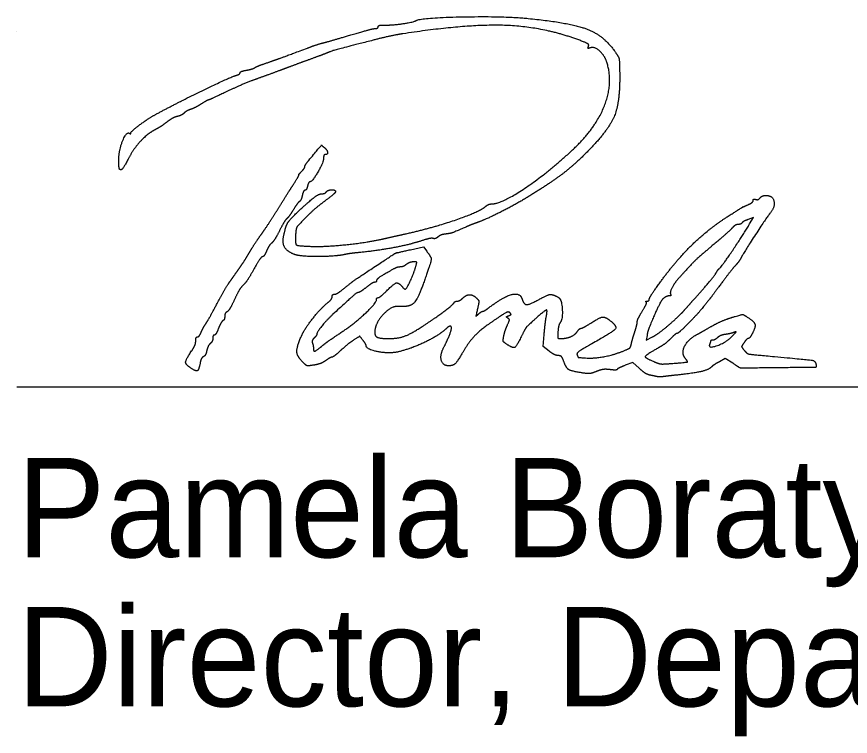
# Model space of a CAD drawing. Extents: x 0 to 34, y 0 to 22.
# Drawn here: x 24.5 to 25.674, y 7.199 to 8.213 of the extents above; entities that cross this region are included whole.
import ezdxf

# ---------------------------------------------------------------- set-up
doc = ezdxf.new("R2010")
doc.units = 0
doc.layers.add('SH_Data', color=7, linetype='Continuous')
doc.layers.add('SH_Text', color=7, linetype='Continuous')

msp = doc.modelspace()

# ---------------------------------------------------------------- linework, layer by layer
at = {"layer": 'SH_Data'}
for p, q in [((24.5, 8.191), (24.5, 8.191)), ((24.5, 7.691), (28, 7.691))]:
    msp.add_line(p, q, dxfattribs=at)
at = {"layer": 'SH_Text'}
for points in [[(25.5318, 7.9205), (25.5372, 7.9294), (25.5298, 7.9268)], [(25.0545, 7.8843), (25.0725, 7.8883), (25.0772, 7.8822)], [(25.2494, 7.7415), (25.2411, 7.7478), (25.2426, 7.7649)], [(25.3874, 7.7635), (25.3864, 7.757), (25.3951, 7.7614)], [(25.3764, 7.7172), (25.3672, 7.7254), (25.3567, 7.7214)], [(25.5083, 7.7242), (25.4976, 7.731), (25.4892, 7.7264)]]:
    msp.add_lwpolyline(points, dxfattribs=at)
for points in [[(25.0179, 8.2007), (25.0275, 8.2004), (25.0585, 8.2047), (25.0619, 8.2069)], [(25.0619, 8.2069), (25.0687, 8.2111), (25.1857, 8.2134), (25.2201, 8.21)], [(25.2201, 8.21), (25.2794, 8.2041), (25.3269, 8.1858), (25.3427, 8.1628)], [(24.9721, 8.1873), (24.9882, 8.192), (25.0031, 8.1959), (25.0051, 8.1959)], [(25.0051, 8.1959), (25.0072, 8.1959), (25.0089, 8.1971), (25.0089, 8.1984)], [(25.0089, 8.1984), (25.0089, 8.1998), (25.0129, 8.2008), (25.0179, 8.2007)], [(25.2926, 8.1792), (25.242, 8.1982), (25.1341, 8.2022), (25.0437, 8.1884)], [(24.9333, 8.1761), (24.9386, 8.1775), (24.9561, 8.1825), (24.9721, 8.1873)], [(25.0437, 8.1884), (25.0345, 8.187), (25.0145, 8.1827), (24.9993, 8.1787)], [(24.8529, 8.1477), (24.8676, 8.1528), (24.8741, 8.1552), (24.9093, 8.1683)], [(24.9093, 8.1683), (24.9172, 8.1713), (24.928, 8.1748), (24.9333, 8.1761)], [(24.9993, 8.1787), (24.9483, 8.1655), (24.944, 8.1643), (24.9333, 8.1599)], [(25.3049, 8.1706), (25.3059, 8.1731), (25.3024, 8.1755), (25.2926, 8.1792)], [(25.3073, 8.1685), (25.3047, 8.1675), (25.304, 8.1682), (25.3049, 8.1706)], [(25.3307, 8.1486), (25.3274, 8.1584), (25.313, 8.1707), (25.3073, 8.1685)], [(24.9333, 8.1599), (24.9307, 8.1589), (24.9204, 8.1551), (24.9105, 8.1515)], [(25.3427, 8.1628), (25.3476, 8.1555), (25.3486, 8.1512), (25.3489, 8.1333)], [(24.8349, 8.1405), (24.8362, 8.1415), (24.8443, 8.1448), (24.8529, 8.1477)], [(24.9105, 8.1515), (24.9006, 8.1479), (24.8855, 8.1423), (24.8769, 8.1391)], [(25.2852, 8.0274), (25.3161, 8.0568), (25.34, 8.1204), (25.3307, 8.1486)], [(24.8091, 8.1299), (24.8121, 8.1308), (24.8145, 8.1324), (24.8145, 8.1334)], [(24.8145, 8.1334), (24.8145, 8.1345), (24.8185, 8.1362), (24.8235, 8.1371)], [(24.8235, 8.1371), (24.8284, 8.138), (24.8336, 8.1396), (24.8349, 8.1405)], [(24.8769, 8.1391), (24.8683, 8.1358), (24.8521, 8.1299), (24.8409, 8.1259)], [(25.3489, 8.1333), (25.3496, 8.0926), (25.3335, 8.0529), (25.3041, 8.023)], [(24.6969, 8.0755), (24.7271, 8.0918), (24.8007, 8.1274), (24.8091, 8.1299)], [(24.8409, 8.1259), (24.8297, 8.1219), (24.8093, 8.1134), (24.7957, 8.1069)], [(24.7957, 8.1069), (24.782, 8.1004), (24.7704, 8.0951), (24.7698, 8.0951)], [(24.7598, 8.0895), (24.7549, 8.0864), (24.7482, 8.083), (24.745, 8.082)], [(24.7698, 8.0951), (24.7693, 8.0951), (24.7648, 8.0926), (24.7598, 8.0895)], [(24.6609, 8.0489), (24.6609, 8.0511), (24.6863, 8.0698), (24.6969, 8.0755)], [(24.7358, 8.0768), (24.734, 8.075), (24.7297, 8.0728), (24.7261, 8.072)], [(24.745, 8.082), (24.7418, 8.0809), (24.7376, 8.0786), (24.7358, 8.0768)], [(24.7113, 8.0639), (24.7067, 8.0603), (24.6995, 8.0557), (24.6954, 8.0536)], [(24.7261, 8.072), (24.7226, 8.0711), (24.7159, 8.0675), (24.7113, 8.0639)], [(24.6954, 8.0536), (24.685, 8.0482), (24.6651, 8.0274), (24.6589, 8.0153)], [(24.6437, 8.0111), (24.6438, 8.0242), (24.6545, 8.0508), (24.6586, 8.0483)], [(24.6586, 8.0483), (24.6599, 8.0475), (24.6609, 8.0478), (24.6609, 8.0489)], [(24.9111, 8.01), (24.9296, 8.0321), (24.9289, 8.0316), (24.933, 8.0282)], [(24.933, 8.0282), (24.9373, 8.0246), (24.9382, 8.0183), (24.9345, 8.0183)], [(25.1685, 7.9487), (25.1826, 7.9487), (25.2507, 7.9946), (25.2852, 8.0274)], [(24.9345, 8.0183), (24.9332, 8.0183), (24.9321, 8.0161), (24.9321, 8.0133)], [(25.3041, 8.023), (25.2855, 8.0041), (25.2531, 7.9792), (25.2226, 7.9603)], [(24.6451, 7.9973), (24.6443, 7.9981), (24.6437, 8.0043), (24.6437, 8.0111)], [(24.6589, 8.0153), (24.6522, 8.0024), (24.6469, 7.9955), (24.6451, 7.9973)], [(24.9057, 8.0013), (24.9057, 8.0025), (24.9081, 8.0064), (24.9111, 8.01)], [(24.9321, 8.0133), (24.9321, 8.0077), (24.9162, 7.9799), (24.913, 7.9799)], [(24.8971, 7.9895), (24.8966, 7.9895), (24.8983, 7.9917), (24.9009, 7.9943)], [(24.9009, 7.9943), (24.9035, 7.997), (24.9057, 8.0001), (24.9057, 8.0013)], [(24.8881, 7.9739), (24.8937, 7.9825), (24.8977, 7.9895), (24.8971, 7.9895)], [(24.8661, 7.9389), (24.8727, 7.9495), (24.8826, 7.9653), (24.8881, 7.9739)], [(24.9095, 7.9739), (24.9087, 7.9706), (24.907, 7.9679), (24.9058, 7.9679)], [(24.913, 7.9799), (24.9119, 7.9799), (24.9103, 7.9772), (24.9095, 7.9739)], [(24.8973, 7.939), (24.913, 7.9536), (24.9258, 7.9631), (24.9297, 7.9631)], [(24.9021, 7.9608), (24.9012, 7.9568), (24.8995, 7.953), (24.8982, 7.9522)], [(24.9058, 7.9679), (24.9047, 7.9679), (24.903, 7.9647), (24.9021, 7.9608)], [(24.9297, 7.9631), (24.9322, 7.9631), (24.9349, 7.9642), (24.9357, 7.9655)], [(24.9489, 7.9659), (24.9489, 7.9648), (24.9421, 7.9589), (24.9339, 7.9528)], [(24.9357, 7.9655), (24.9375, 7.9684), (24.9489, 7.9688), (24.9489, 7.9659)], [(25.2226, 7.9603), (25.2035, 7.9485), (25.1622, 7.9275), (25.1481, 7.9224)], [(25.5403, 7.9551), (25.5422, 7.9544), (25.545, 7.9554), (25.5466, 7.9573)], [(25.5466, 7.9573), (25.5482, 7.9592), (25.5519, 7.9607), (25.5548, 7.9607)], [(25.5548, 7.9607), (25.5643, 7.9607), (25.568, 7.9447), (25.5606, 7.9357)], [(24.8982, 7.9522), (24.8969, 7.9514), (24.8931, 7.9462), (24.8897, 7.9407)], [(24.9339, 7.9528), (24.9256, 7.9467), (24.9131, 7.9358), (24.9061, 7.9287)], [(25.0485, 7.9068), (25.0854, 7.915), (25.1517, 7.9379), (25.1603, 7.9454)], [(25.1603, 7.9454), (25.1624, 7.9472), (25.1661, 7.9487), (25.1685, 7.9487)], [(25.5001, 7.9304), (25.5191, 7.9426), (25.5209, 7.9437), (25.5291, 7.9474)], [(25.5291, 7.9474), (25.5334, 7.9493), (25.5369, 7.9521), (25.5369, 7.9537)], [(25.5369, 7.9537), (25.5369, 7.9552), (25.5384, 7.9559), (25.5403, 7.9551)], [(24.8443, 7.9059), (24.8497, 7.9134), (24.8595, 7.9282), (24.8661, 7.9389)], [(24.876, 7.9043), (24.8787, 7.9174), (24.8849, 7.9274), (24.8973, 7.939)], [(24.8897, 7.9407), (24.8863, 7.9352), (24.8822, 7.9296), (24.8806, 7.9283)], [(25.5606, 7.9357), (25.5564, 7.9307), (25.5236, 7.8802), (25.5204, 7.8741)], [(24.8806, 7.9283), (24.8789, 7.927), (24.8742, 7.9194), (24.8702, 7.9114)], [(24.9061, 7.9287), (24.8954, 7.9177), (24.8932, 7.914), (24.8927, 7.9058)], [(25.1481, 7.9224), (25.1435, 7.9207), (25.1364, 7.918), (25.1325, 7.9162)], [(25.4055, 7.8378), (25.4278, 7.8686), (25.4728, 7.9127), (25.5001, 7.9304)], [(25.5212, 7.9221), (25.5204, 7.9209), (25.518, 7.9199), (25.5158, 7.9199)], [(25.5298, 7.9268), (25.5258, 7.9254), (25.5219, 7.9233), (25.5212, 7.9221)], [(24.8702, 7.9114), (24.8662, 7.9034), (24.8611, 7.8954), (24.859, 7.8936)], [(25.1325, 7.9162), (25.1154, 7.9088), (25.1105, 7.9071), (25.1039, 7.9063)], [(25.507, 7.9145), (25.5043, 7.9116), (25.4918, 7.9005), (25.4793, 7.89)], [(25.489, 7.8575), (25.4918, 7.8595), (25.52, 7.901), (25.5318, 7.9205)], [(25.5158, 7.9199), (25.5136, 7.9199), (25.5097, 7.9175), (25.507, 7.9145)], [(24.8276, 7.8803), (24.8315, 7.8869), (24.839, 7.8985), (24.8443, 7.9059)], [(24.8913, 7.8775), (24.8809, 7.8814), (24.8737, 7.8938), (24.876, 7.9043)], [(24.8927, 7.9058), (24.8918, 7.8923), (24.8959, 7.8895), (24.9165, 7.8889)], [(24.9165, 7.8889), (24.9358, 7.8884), (24.9936, 7.8945), (25.0149, 7.8993)], [(25.0149, 7.8993), (25.0228, 7.9011), (25.0379, 7.9045), (25.0485, 7.9068)], [(25.0863, 7.9001), (25.0846, 7.9007), (25.0765, 7.899), (25.0683, 7.8963)], [(25.0931, 7.9022), (25.091, 7.9004), (25.0879, 7.8995), (25.0863, 7.9001)], [(25.1039, 7.9063), (25.1, 7.9059), (25.0952, 7.9041), (25.0931, 7.9022)], [(24.859, 7.8936), (24.8568, 7.8918), (24.8535, 7.8867), (24.8517, 7.8823)], [(25.0683, 7.8963), (25.0518, 7.891), (25.0067, 7.8826), (24.9829, 7.8803)], [(25.4793, 7.89), (25.4597, 7.8734), (25.448, 7.862), (25.4313, 7.8432)], [(24.8146, 7.8597), (24.8179, 7.8645), (24.8238, 7.8737), (24.8276, 7.8803)], [(24.8517, 7.8823), (24.8498, 7.8779), (24.8473, 7.8743), (24.846, 7.8743)], [(24.9625, 7.8776), (24.9488, 7.8746), (24.8993, 7.8745), (24.8913, 7.8775)], [(24.9829, 7.8803), (24.9746, 7.8795), (24.9654, 7.8783), (24.9625, 7.8776)], [(25.0005, 7.8579), (25.0322, 7.8789), (25.0335, 7.8796), (25.0545, 7.8843)], [(25.0772, 7.8822), (25.0838, 7.8734), (25.0836, 7.8685), (25.0759, 7.846)], [(24.846, 7.8743), (24.8447, 7.8743), (24.8393, 7.8664), (24.8339, 7.8568)], [(25.0486, 7.8635), (25.0461, 7.8615), (25.0421, 7.8599), (25.0399, 7.8599)], [(25.0585, 7.8671), (25.0557, 7.867), (25.0512, 7.8654), (25.0486, 7.8635)], [(25.0618, 7.8605), (25.0635, 7.8663), (25.0631, 7.8671), (25.0585, 7.8671)], [(25.5204, 7.8741), (25.5187, 7.8706), (25.5148, 7.8652), (25.5118, 7.8619)], [(24.801, 7.8405), (24.8051, 7.8463), (24.8112, 7.8549), (24.8146, 7.8597)], [(24.8339, 7.8568), (24.8286, 7.8471), (24.8219, 7.8371), (24.8191, 7.8346)], [(24.9613, 7.83), (24.975, 7.841), (24.973, 7.8396), (25.0005, 7.8579)], [(25.0302, 7.8568), (25.0158, 7.8489), (25.0065, 7.8425), (25.0065, 7.8405)], [(25.0399, 7.8599), (25.0377, 7.8599), (25.0333, 7.8585), (25.0302, 7.8568)], [(25.0471, 7.8287), (25.0489, 7.8287), (25.0587, 7.8499), (25.0618, 7.8605)], [(25.4538, 7.8146), (25.4691, 7.8317), (25.4827, 7.8481), (25.4851, 7.8524)], [(25.4851, 7.8524), (25.4863, 7.8546), (25.4881, 7.8569), (25.489, 7.8575)], [(25.5118, 7.8619), (25.5088, 7.8587), (25.4999, 7.8474), (25.492, 7.8367)], [(24.7821, 7.8083), (24.7884, 7.8202), (24.7969, 7.8347), (24.801, 7.8405)], [(25.0065, 7.8405), (25.0065, 7.8393), (25.0053, 7.8383), (25.0038, 7.8383)], [(25.0759, 7.846), (25.0656, 7.8161), (25.0537, 7.803), (25.0377, 7.8044)], [(25.4313, 7.8432), (25.4255, 7.8366), (25.4192, 7.8237), (25.4206, 7.8213)], [(24.8191, 7.8346), (24.8162, 7.832), (24.8107, 7.8229), (24.8068, 7.8143)], [(24.9475, 7.8215), (24.9493, 7.8215), (24.9555, 7.8253), (24.9613, 7.83)], [(24.9921, 7.8311), (24.9871, 7.8272), (24.9821, 7.8239), (24.981, 7.8239)], [(25.0038, 7.8383), (25.0024, 7.8383), (24.9971, 7.8351), (24.9921, 7.8311)], [(25.0209, 7.8263), (25.031, 7.8365), (25.0376, 7.8383), (25.0425, 7.8323)], [(25.0425, 7.8323), (25.0441, 7.8304), (25.0462, 7.8287), (25.0471, 7.8287)], [(25.3905, 7.8145), (25.3905, 7.8159), (25.3972, 7.8264), (25.4055, 7.8378)], [(25.492, 7.8367), (25.4841, 7.8261), (25.4765, 7.8159), (25.475, 7.814)], [(24.9387, 7.8103), (24.9417, 7.8127), (24.9441, 7.8162), (24.9441, 7.8181)], [(24.9441, 7.8181), (24.9441, 7.82), (24.9456, 7.8215), (24.9475, 7.8215)], [(24.981, 7.8239), (24.9791, 7.8239), (24.9706, 7.8167), (24.9453, 7.7934)], [(25.0065, 7.8136), (25.0065, 7.8153), (25.0076, 7.8167), (25.0089, 7.8167)], [(25.0089, 7.8167), (25.0102, 7.8167), (25.0156, 7.8211), (25.0209, 7.8263)], [(25.1277, 7.8158), (25.1326, 7.8208), (25.1426, 7.8209), (25.1475, 7.8159)], [(25.1657, 7.8033), (25.1859, 7.8184), (25.2086, 7.824), (25.2116, 7.8146)], [(25.2354, 7.8142), (25.2474, 7.8208), (25.2546, 7.8216), (25.2628, 7.817)], [(25.2628, 7.817), (25.2672, 7.8145), (25.2689, 7.7865), (25.265, 7.7813)], [(25.4184, 7.8191), (25.412, 7.8191), (25.4025, 7.804), (25.3904, 7.7747)], [(25.4206, 7.8213), (25.4214, 7.8201), (25.4204, 7.8191), (25.4184, 7.8191)], [(24.7667, 7.7807), (24.7689, 7.784), (24.7759, 7.7965), (24.7821, 7.8083)], [(24.8068, 7.8143), (24.8029, 7.8058), (24.7981, 7.7979), (24.7963, 7.7968)], [(24.9006, 7.7621), (24.9051, 7.7725), (24.9283, 7.802), (24.9387, 7.8103)], [(24.9604, 7.7702), (24.976, 7.7806), (25.0065, 7.8093), (25.0065, 7.8136)], [(25.0377, 7.8044), (25.0273, 7.8053), (25.0041, 7.7799), (25.0041, 7.7676)], [(25.0725, 7.7771), (25.0911, 7.7894), (25.1135, 7.8061), (25.1152, 7.8089)], [(25.1152, 7.8089), (25.1163, 7.8106), (25.1186, 7.8119), (25.1204, 7.8119)], [(25.1204, 7.8119), (25.1223, 7.8119), (25.1255, 7.8137), (25.1277, 7.8158)], [(25.1475, 7.8159), (25.1507, 7.8128), (25.1509, 7.8103), (25.1488, 7.8011)], [(25.2116, 7.8146), (25.214, 7.807), (25.2221, 7.8069), (25.2354, 7.8142)], [(25.3807, 7.7976), (25.3846, 7.8039), (25.3871, 7.8097), (25.3863, 7.8105)], [(25.3863, 7.8105), (25.3855, 7.8113), (25.3862, 7.8119), (25.3877, 7.8119)], [(25.3877, 7.8119), (25.3892, 7.8119), (25.3905, 7.8131), (25.3905, 7.8145)], [(25.4382, 7.7971), (25.4413, 7.8006), (25.4484, 7.8085), (25.4538, 7.8146)], [(25.475, 7.814), (25.4617, 7.7976), (25.4572, 7.7925), (25.4453, 7.7803)], [(24.7963, 7.7968), (24.7944, 7.7958), (24.7929, 7.7929), (24.7929, 7.7904)], [(24.9453, 7.7934), (24.9362, 7.785), (24.9225, 7.768), (24.9225, 7.765)], [(25.1488, 7.8011), (25.1465, 7.7909), (25.1466, 7.7904), (25.1504, 7.7939)], [(25.1504, 7.7939), (25.1526, 7.7959), (25.1553, 7.7975), (25.1562, 7.7975)], [(25.1562, 7.7975), (25.1572, 7.7975), (25.1615, 7.8001), (25.1657, 7.8033)], [(25.1943, 7.7955), (25.1925, 7.7973), (25.1866, 7.7945), (25.1741, 7.786)], [(25.1927, 7.7913), (25.1957, 7.7924), (25.1962, 7.7936), (25.1943, 7.7955)], [(25.2455, 7.7897), (25.2474, 7.7992), (25.2447, 7.7996), (25.2354, 7.7914)], [(25.3737, 7.7829), (25.3737, 7.7847), (25.3769, 7.7914), (25.3807, 7.7976)], [(25.4181, 7.7783), (25.426, 7.7851), (25.4351, 7.7936), (25.4382, 7.7971)], [(25.5074, 7.789), (25.5215, 7.7932), (25.5226, 7.7932), (25.5285, 7.7894)], [(24.7904, 7.7843), (24.789, 7.7834), (24.7862, 7.7785), (24.7841, 7.7733)], [(24.7929, 7.7904), (24.7929, 7.7879), (24.7918, 7.7851), (24.7904, 7.7843)], [(25.1741, 7.786), (25.1544, 7.7726), (25.1372, 7.7555), (25.1289, 7.7411)], [(25.1915, 7.7878), (25.1893, 7.7892), (25.1896, 7.7901), (25.1927, 7.7913)], [(25.1908, 7.778), (25.1937, 7.7842), (25.1938, 7.7864), (25.1915, 7.7878)], [(25.2354, 7.7914), (25.2195, 7.7774), (25.2158, 7.773), (25.2103, 7.7616)], [(25.2426, 7.7649), (25.2434, 7.7743), (25.2447, 7.7854), (25.2455, 7.7897)], [(25.265, 7.7813), (25.2637, 7.7797), (25.2624, 7.774), (25.262, 7.7687)], [(25.3363, 7.7837), (25.346, 7.7761), (25.3391, 7.7682), (25.3076, 7.7505)], [(25.3081, 7.7807), (25.321, 7.789), (25.3286, 7.7898), (25.3363, 7.7837)], [(25.3702, 7.7687), (25.3721, 7.7747), (25.3737, 7.781), (25.3737, 7.7829)], [(25.4781, 7.7763), (25.486, 7.7808), (25.4992, 7.7865), (25.5074, 7.789)], [(25.5285, 7.7894), (25.5381, 7.7831), (25.5405, 7.7757), (25.5359, 7.7667)], [(24.7598, 7.7681), (24.7614, 7.7718), (24.7645, 7.7774), (24.7667, 7.7807)], [(24.7841, 7.7733), (24.7821, 7.7682), (24.7794, 7.7639), (24.7782, 7.7639)], [(24.9289, 7.7478), (24.9364, 7.7539), (24.9417, 7.7576), (24.9604, 7.7702)], [(25.024, 7.7591), (25.0371, 7.7591), (25.0562, 7.7662), (25.0725, 7.7771)], [(25.1045, 7.7729), (25.0949, 7.7638), (25.0562, 7.745), (25.0377, 7.7405)], [(25.1015, 7.7471), (25.1056, 7.7548), (25.1121, 7.7711), (25.1121, 7.7738)], [(25.1121, 7.7738), (25.1121, 7.7769), (25.1081, 7.7764), (25.1045, 7.7729)], [(25.1857, 7.7623), (25.1865, 7.7665), (25.1888, 7.7736), (25.1908, 7.778)], [(25.289, 7.7687), (25.2908, 7.7713), (25.2933, 7.7735), (25.2945, 7.7735)], [(25.2945, 7.7735), (25.2957, 7.7735), (25.3018, 7.7768), (25.3081, 7.7807)], [(25.3904, 7.7747), (25.3893, 7.7721), (25.388, 7.767), (25.3874, 7.7635)], [(25.3951, 7.7614), (25.3998, 7.7639), (25.4102, 7.7715), (25.4181, 7.7783)], [(25.4453, 7.7803), (25.4378, 7.7726), (25.4308, 7.7663), (25.4297, 7.7663)], [(25.4585, 7.7653), (25.4614, 7.7668), (25.4702, 7.7718), (25.4781, 7.7763)], [(24.7521, 7.7559), (24.7521, 7.759), (24.7532, 7.7615), (24.7545, 7.7615)], [(24.7545, 7.7615), (24.7559, 7.7615), (24.7583, 7.7645), (24.7598, 7.7681)], [(24.7761, 7.7594), (24.7761, 7.757), (24.7745, 7.7536), (24.7727, 7.7521)], [(24.7782, 7.7639), (24.7771, 7.7639), (24.7761, 7.7619), (24.7761, 7.7594)], [(24.9023, 7.7264), (24.8947, 7.734), (24.8941, 7.7468), (24.9006, 7.7621)], [(24.9188, 7.7599), (24.9167, 7.7578), (24.9156, 7.7546), (24.9164, 7.7526)], [(24.9225, 7.765), (24.9225, 7.7642), (24.9208, 7.7619), (24.9188, 7.7599)], [(24.9762, 7.758), (24.968, 7.7526), (24.9654, 7.7506), (24.9542, 7.7405)], [(24.9875, 7.7566), (24.983, 7.7624), (24.983, 7.7624), (24.9762, 7.758)], [(25.0041, 7.7676), (25.0041, 7.7625), (25.0119, 7.7591), (25.024, 7.7591)], [(25.1903, 7.7508), (25.1853, 7.7541), (25.1845, 7.7561), (25.1857, 7.7623)], [(25.2103, 7.7616), (25.2036, 7.7479), (25.1988, 7.7453), (25.1903, 7.7508)], [(25.262, 7.7687), (25.2615, 7.7612), (25.2622, 7.7591), (25.2654, 7.7591)], [(25.2654, 7.7591), (25.2737, 7.7591), (25.2857, 7.764), (25.289, 7.7687)], [(25.3654, 7.7517), (25.3661, 7.7551), (25.3683, 7.7628), (25.3702, 7.7687)], [(25.4211, 7.7594), (25.4175, 7.7556), (25.4094, 7.7494), (25.4031, 7.7458)], [(25.4297, 7.7663), (25.4286, 7.7663), (25.4247, 7.7632), (25.4211, 7.7594)], [(25.4415, 7.7309), (25.4354, 7.7383), (25.4452, 7.7581), (25.4585, 7.7653)], [(25.4755, 7.751), (25.473, 7.7445), (25.4984, 7.7534), (25.5069, 7.7621)], [(25.4865, 7.7603), (25.4843, 7.7584), (25.4813, 7.7567), (25.4797, 7.7567)], [(25.4975, 7.7649), (25.4936, 7.7644), (25.4887, 7.7623), (25.4865, 7.7603)], [(25.5093, 7.7676), (25.5067, 7.7666), (25.5013, 7.7654), (25.4975, 7.7649)], [(25.5069, 7.7621), (25.5124, 7.7676), (25.513, 7.769), (25.5093, 7.7676)], [(25.5299, 7.7591), (25.5288, 7.7591), (25.5261, 7.7565), (25.524, 7.7533)], [(25.5359, 7.7667), (25.5337, 7.7625), (25.531, 7.7591), (25.5299, 7.7591)], [(24.7463, 7.7416), (24.7495, 7.7464), (24.7521, 7.7528), (24.7521, 7.7559)], [(24.7727, 7.7521), (24.7708, 7.7505), (24.7685, 7.746), (24.7676, 7.742)], [(24.9164, 7.7526), (24.9171, 7.7507), (24.9177, 7.7476), (24.9177, 7.7457)], [(24.9177, 7.7457), (24.9177, 7.7409), (24.9211, 7.7415), (24.9289, 7.7478)], [(24.992, 7.7492), (24.992, 7.75), (24.99, 7.7534), (24.9875, 7.7566)], [(25.0377, 7.7405), (25.0248, 7.7374), (24.9922, 7.7436), (24.992, 7.7492)], [(25.1082, 7.7207), (25.0998, 7.7207), (25.0958, 7.7365), (25.1015, 7.7471)], [(25.3076, 7.7505), (25.2943, 7.743), (25.2881, 7.7382), (25.289, 7.736)], [(25.3527, 7.741), (25.3615, 7.7444), (25.3645, 7.7469), (25.3654, 7.7517)], [(25.4031, 7.7458), (25.3852, 7.7354), (25.3842, 7.7321), (25.3971, 7.7266)], [(25.4769, 7.7557), (25.4769, 7.7552), (25.4763, 7.7531), (25.4755, 7.751)], [(25.4797, 7.7567), (25.4782, 7.7567), (25.4769, 7.7563), (25.4769, 7.7557)], [(25.524, 7.7533), (25.5205, 7.748), (25.5206, 7.7471), (25.5244, 7.7424)], [(24.7446, 7.7179), (24.7376, 7.7228), (24.7381, 7.7295), (24.7463, 7.7416)], [(24.7676, 7.742), (24.7668, 7.7381), (24.7646, 7.7343), (24.7629, 7.7336)], [(24.9542, 7.7405), (24.9494, 7.7362), (24.9446, 7.7327), (24.9435, 7.7327)], [(25.1289, 7.7411), (25.1207, 7.727), (25.1143, 7.7207), (25.1082, 7.7207)], [(25.2624, 7.7351), (25.2599, 7.7351), (25.254, 7.738), (25.2494, 7.7415)], [(25.27, 7.7273), (25.2681, 7.7325), (25.2656, 7.7351), (25.2624, 7.7351)], [(25.289, 7.736), (25.2903, 7.7326), (25.291, 7.7324), (25.3029, 7.7317)], [(25.3029, 7.7317), (25.3134, 7.7311), (25.3396, 7.736), (25.3527, 7.741)], [(25.5244, 7.7424), (25.528, 7.7379), (25.533, 7.7368), (25.5669, 7.7337)], [(24.7583, 7.7244), (24.7564, 7.7146), (24.7522, 7.7127), (24.7446, 7.7179)], [(24.7629, 7.7336), (24.7612, 7.7329), (24.7591, 7.7288), (24.7583, 7.7244)], [(24.9185, 7.7217), (24.9098, 7.7204), (24.9076, 7.721), (24.9023, 7.7264)], [(24.935, 7.728), (24.9314, 7.7254), (24.924, 7.7226), (24.9185, 7.7217)], [(24.9435, 7.7327), (24.9424, 7.7327), (24.9386, 7.7306), (24.935, 7.728)], [(25.2953, 7.7108), (25.2803, 7.7132), (25.2735, 7.7177), (25.27, 7.7273)], [(25.3971, 7.7266), (25.4039, 7.7236), (25.4104, 7.723), (25.4239, 7.7241)], [(25.4239, 7.7241), (25.4434, 7.7257), (25.4452, 7.7264), (25.4415, 7.7309)], [(25.4892, 7.7264), (25.4846, 7.724), (25.4794, 7.7204), (25.4775, 7.7186)], [(25.5549, 7.7177), (25.5192, 7.7174), (25.5188, 7.7174), (25.5083, 7.7242)], [(25.6252, 7.7228), (25.626, 7.7186), (25.624, 7.7185), (25.5549, 7.7177)], [(25.5669, 7.7337), (25.616, 7.7292), (25.6243, 7.7276), (25.6252, 7.7228)], [(25.3164, 7.7128), (25.3094, 7.71), (25.3039, 7.7094), (25.2953, 7.7108)], [(25.3353, 7.7153), (25.3295, 7.7161), (25.3222, 7.7151), (25.3164, 7.7128)], [(25.3454, 7.7156), (25.345, 7.7148), (25.3404, 7.7146), (25.3353, 7.7153)], [(25.3567, 7.7214), (25.3509, 7.7191), (25.3458, 7.7165), (25.3454, 7.7156)], [(25.391, 7.7077), (25.388, 7.7083), (25.3814, 7.7126), (25.3764, 7.7172)], [(25.4775, 7.7186), (25.4738, 7.7149), (25.4523, 7.71), (25.4289, 7.7076)], [(25.4013, 7.7055), (25.3987, 7.7061), (25.394, 7.7071), (25.391, 7.7077)], [(25.4097, 7.7053), (25.4077, 7.7049), (25.4039, 7.705), (25.4013, 7.7055)], [(25.4289, 7.7076), (25.4203, 7.7067), (25.4117, 7.7057), (25.4097, 7.7053)]]:
    msp.add_open_spline(points, degree=2, dxfattribs=at)

# ---------------------------------------------------------------- texts
for s, p in [('Pamela Boratyn', (24.5, 7.451)), ('Director, Department of Transportation', (24.5, 7.241))]:
    msp.add_text(s, height=0.14, dxfattribs=at).set_placement(p)

doc.saveas('drawing.dxf')
